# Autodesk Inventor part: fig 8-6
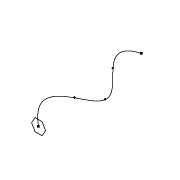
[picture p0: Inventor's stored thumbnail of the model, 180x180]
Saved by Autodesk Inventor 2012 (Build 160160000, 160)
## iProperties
Created: 2006-01
Part Number: fig 8-6
Document SubType Name: Modeling
Designer: CADCIM
Density: 1 g/cm^3
Material: Default
Author: CADCIM
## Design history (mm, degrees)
sketch "Sketch1"
  geometry: 5 further points
  constraints: 5 other
sketch "Sketch2"
  geometry: L1 (-4.728, 0)-(-2.364, 4.094); L2 (-2.364, 4.094)-(2.364, 4.094); L3 (2.364, 4.094)-(4.728, 0); L4 (4.728, 0)-(2.364, -4.094); L5 (2.364, -4.094)-(-2.364, -4.094); L6 (-2.364, -4.094)-(-4.728, 0); 1 further point
  constraints: 12 end point, 13 other
body "Solid1"
